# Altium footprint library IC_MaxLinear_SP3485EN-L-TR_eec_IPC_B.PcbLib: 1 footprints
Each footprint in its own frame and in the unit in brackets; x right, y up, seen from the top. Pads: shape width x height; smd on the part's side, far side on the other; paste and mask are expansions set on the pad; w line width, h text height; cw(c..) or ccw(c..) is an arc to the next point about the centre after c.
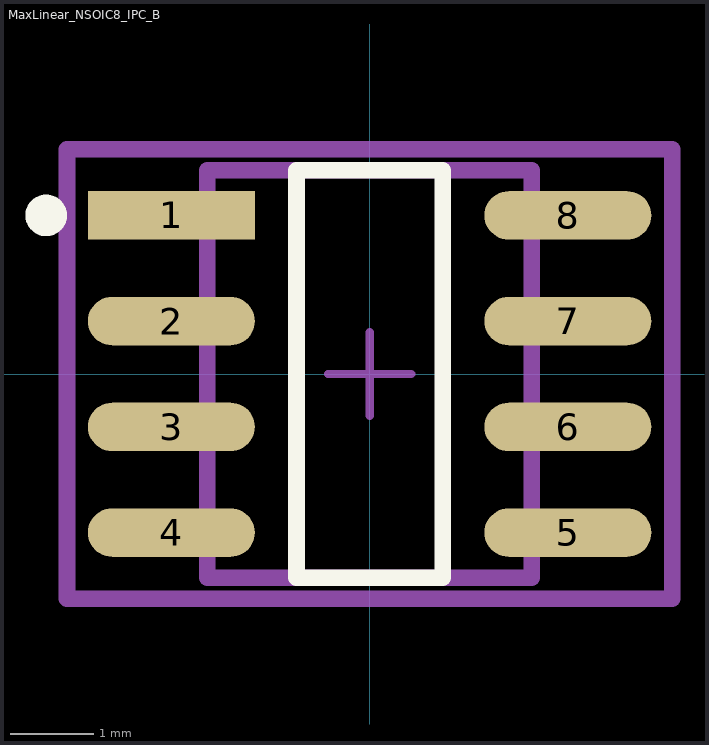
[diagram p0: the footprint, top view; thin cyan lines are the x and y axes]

## MaxLinear_NSOIC8_IPC_B [mil]
pads (8):
  rect 78.99x22.92 smd paste+0 mask+0: 1(-93.79,75)
  rrect100% 78.99x22.92 smd paste+0 mask+0: 2(-93.79,25) 3(-93.79,-25) 4(-93.79,-75) 5(93.79,-75) 6(93.79,-25) 7(93.79,25) 8(93.79,75)
Top Overlay:
  circle w9.84: c-152.97,75 r4.92
  lines w7.87: -34.61,-96.46 34.61,-96.46 34.61,96.46 -34.61,96.46 -34.61,-96.46
Mechanical 10:
  lines w7.87: -143.12,-106.3 143.12,-106.3 143.12,106.3 -143.12,106.3 -143.12,-106.3
  text ".Designator" at 0,7.41 h39.37
Mechanical 12:
  lines w7.87: -76.77,-96.46 76.77,-96.46 76.77,96.46 -76.77,96.46 -76.77,-96.46
Mechanical 15:
  lines w3.94: -19.68,0 19.68,0 ; 0,-19.68 0,19.68
  lines w7.87: -143.12,-106.3 143.12,-106.3 143.12,106.3 -143.12,106.3 -143.12,-106.3
3D body "IC_MaxLinear_SP3485EN-L-TR_eec.STEP": height 10, standoff 0, extent -143.12,-106.3 143.12,106.3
